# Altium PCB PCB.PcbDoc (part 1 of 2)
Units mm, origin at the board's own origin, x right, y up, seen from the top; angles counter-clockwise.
Board outline 106 x 80 mm, 4 copper layers (TOP, GND, SIG, BOTTOM), stack 1.586 mm thick; 94 components, 82 nets, 532 pads, 292 vias.
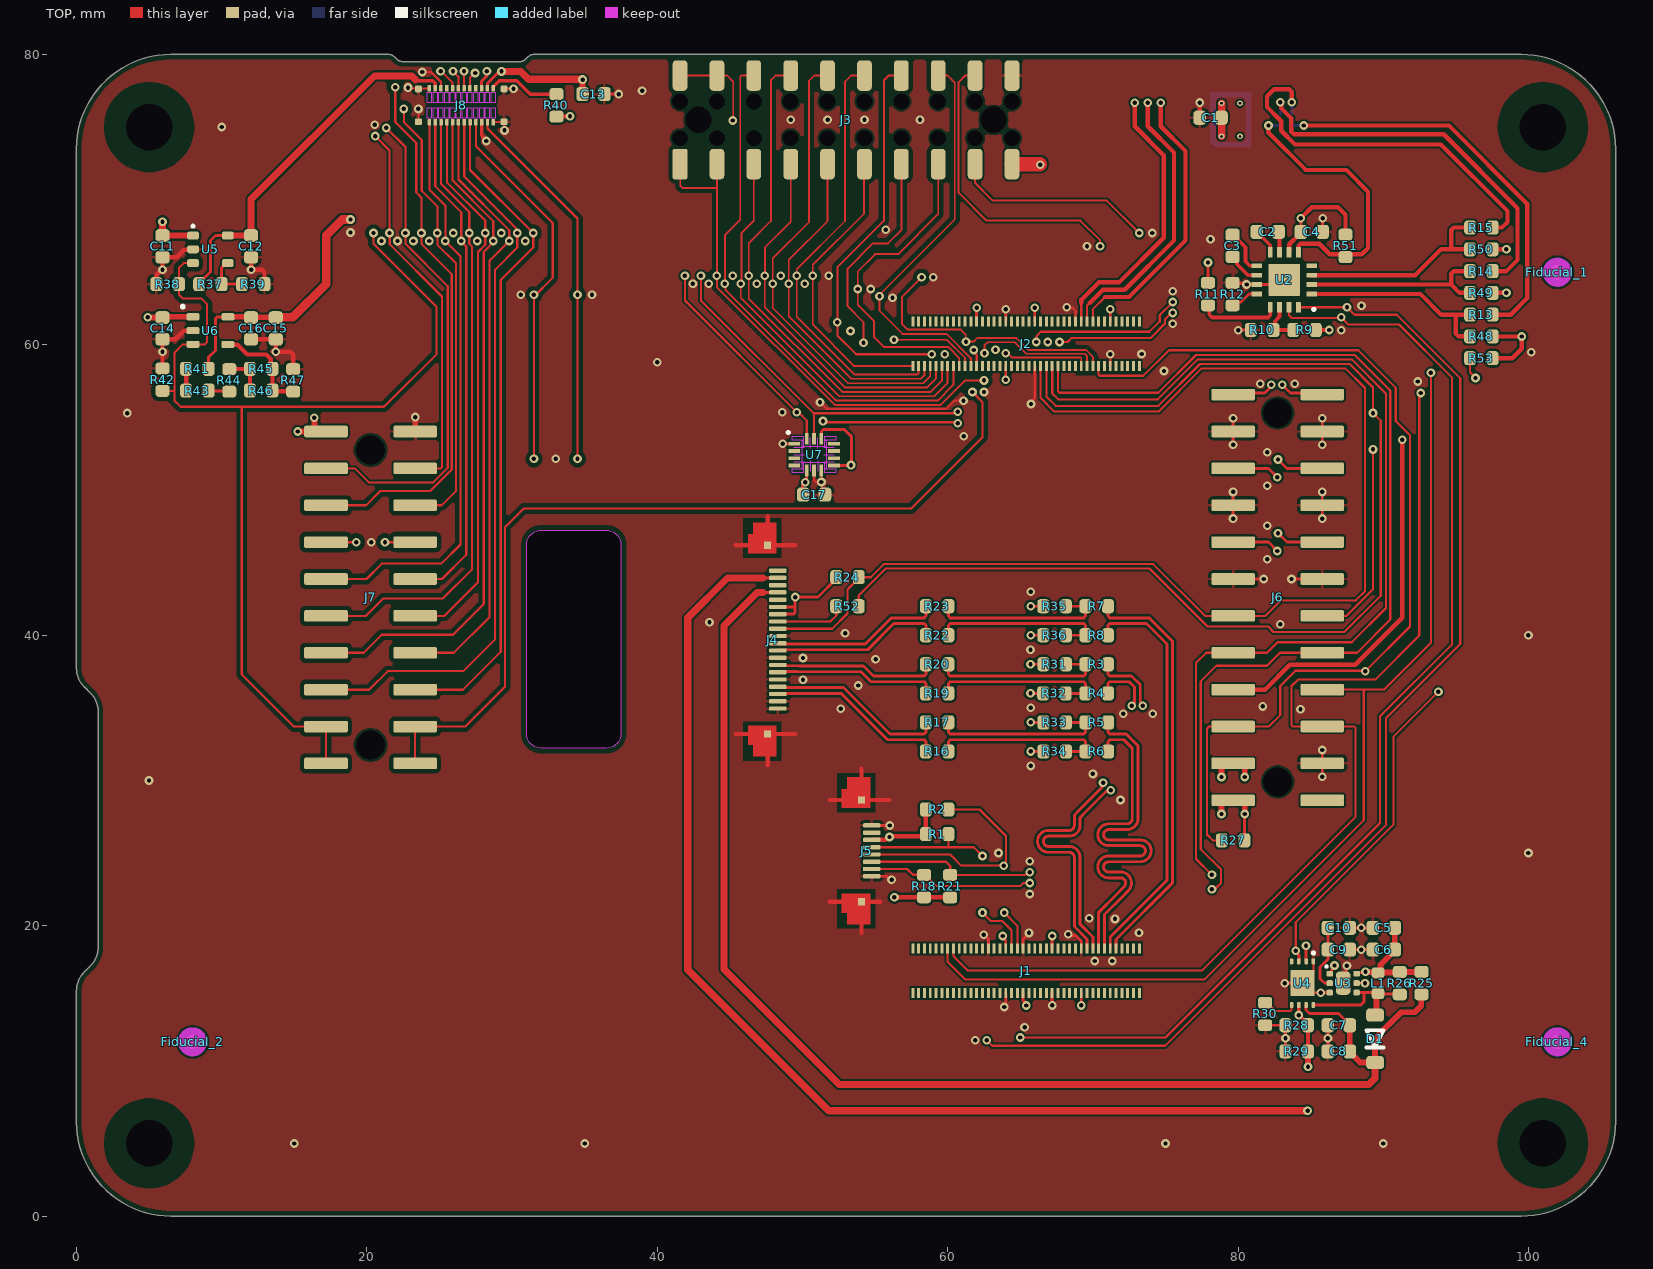
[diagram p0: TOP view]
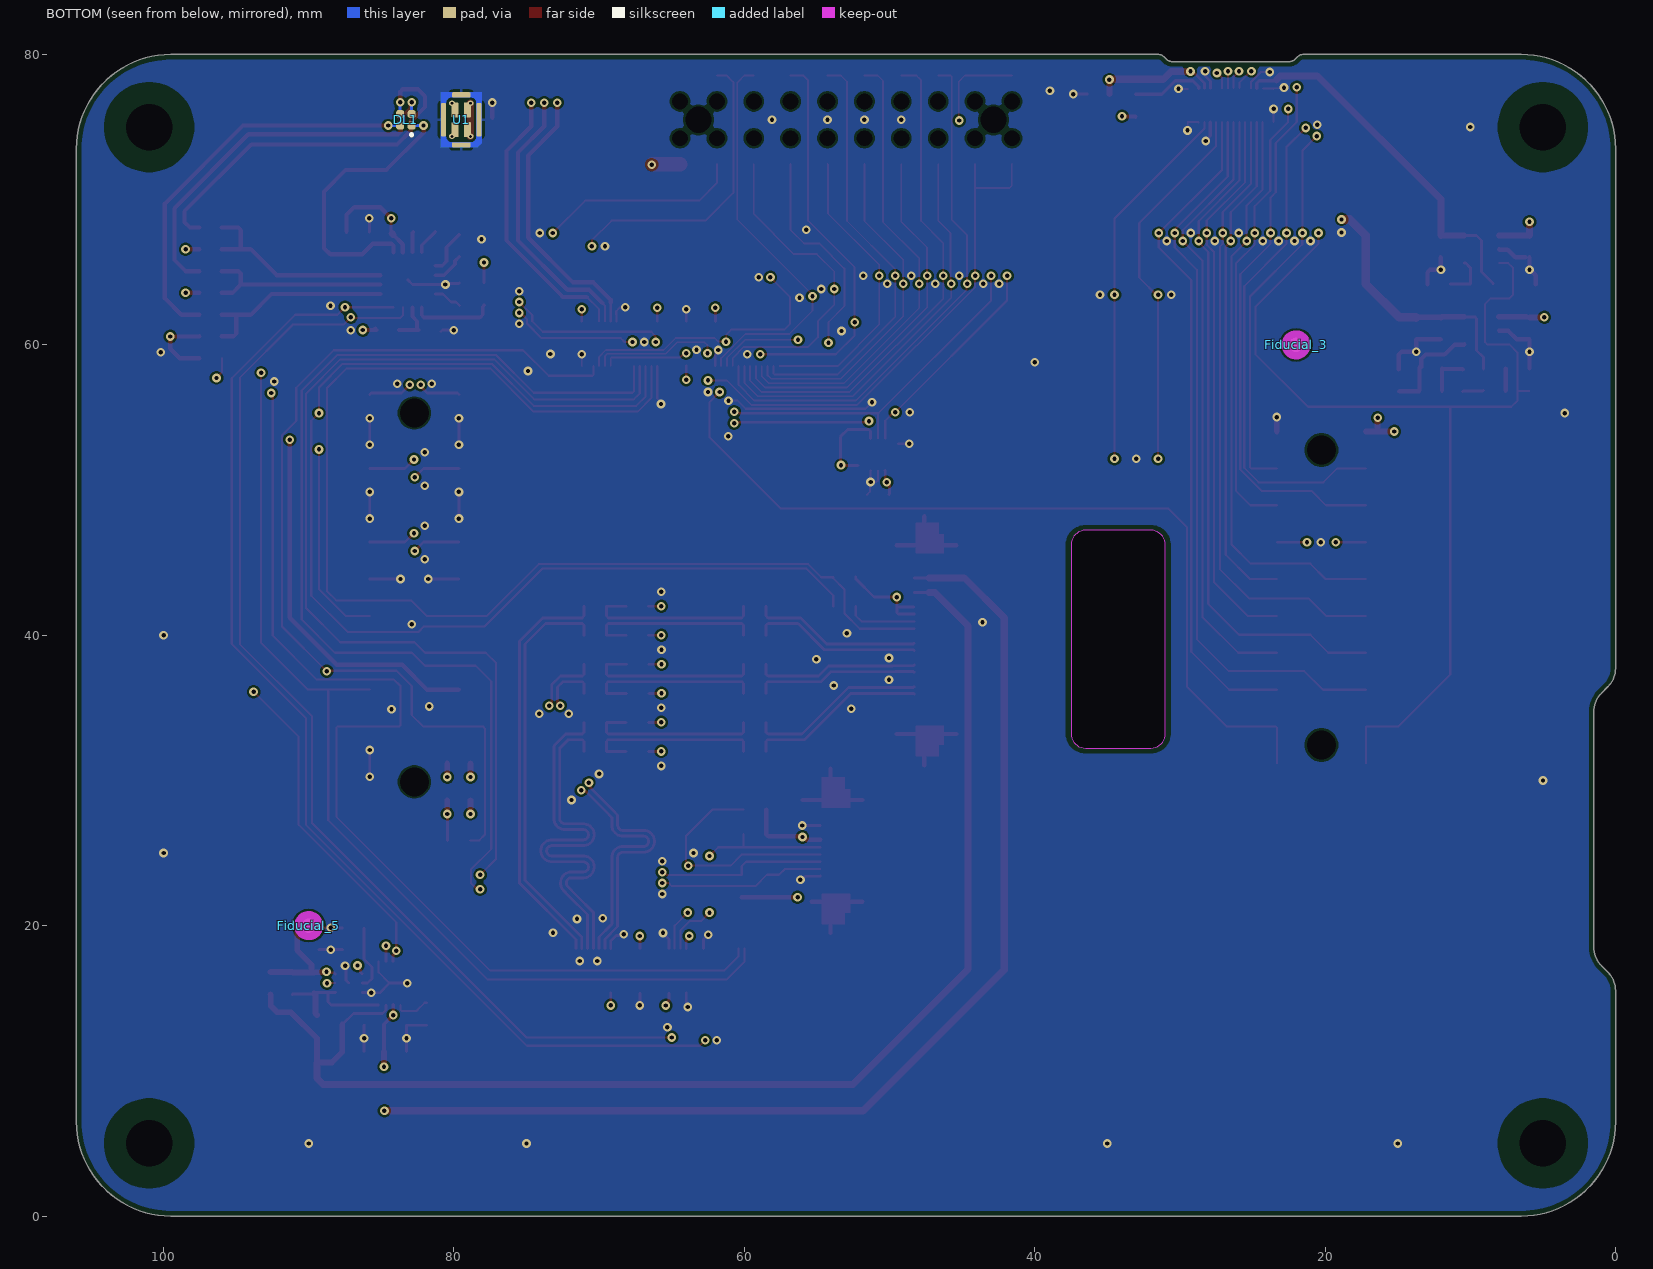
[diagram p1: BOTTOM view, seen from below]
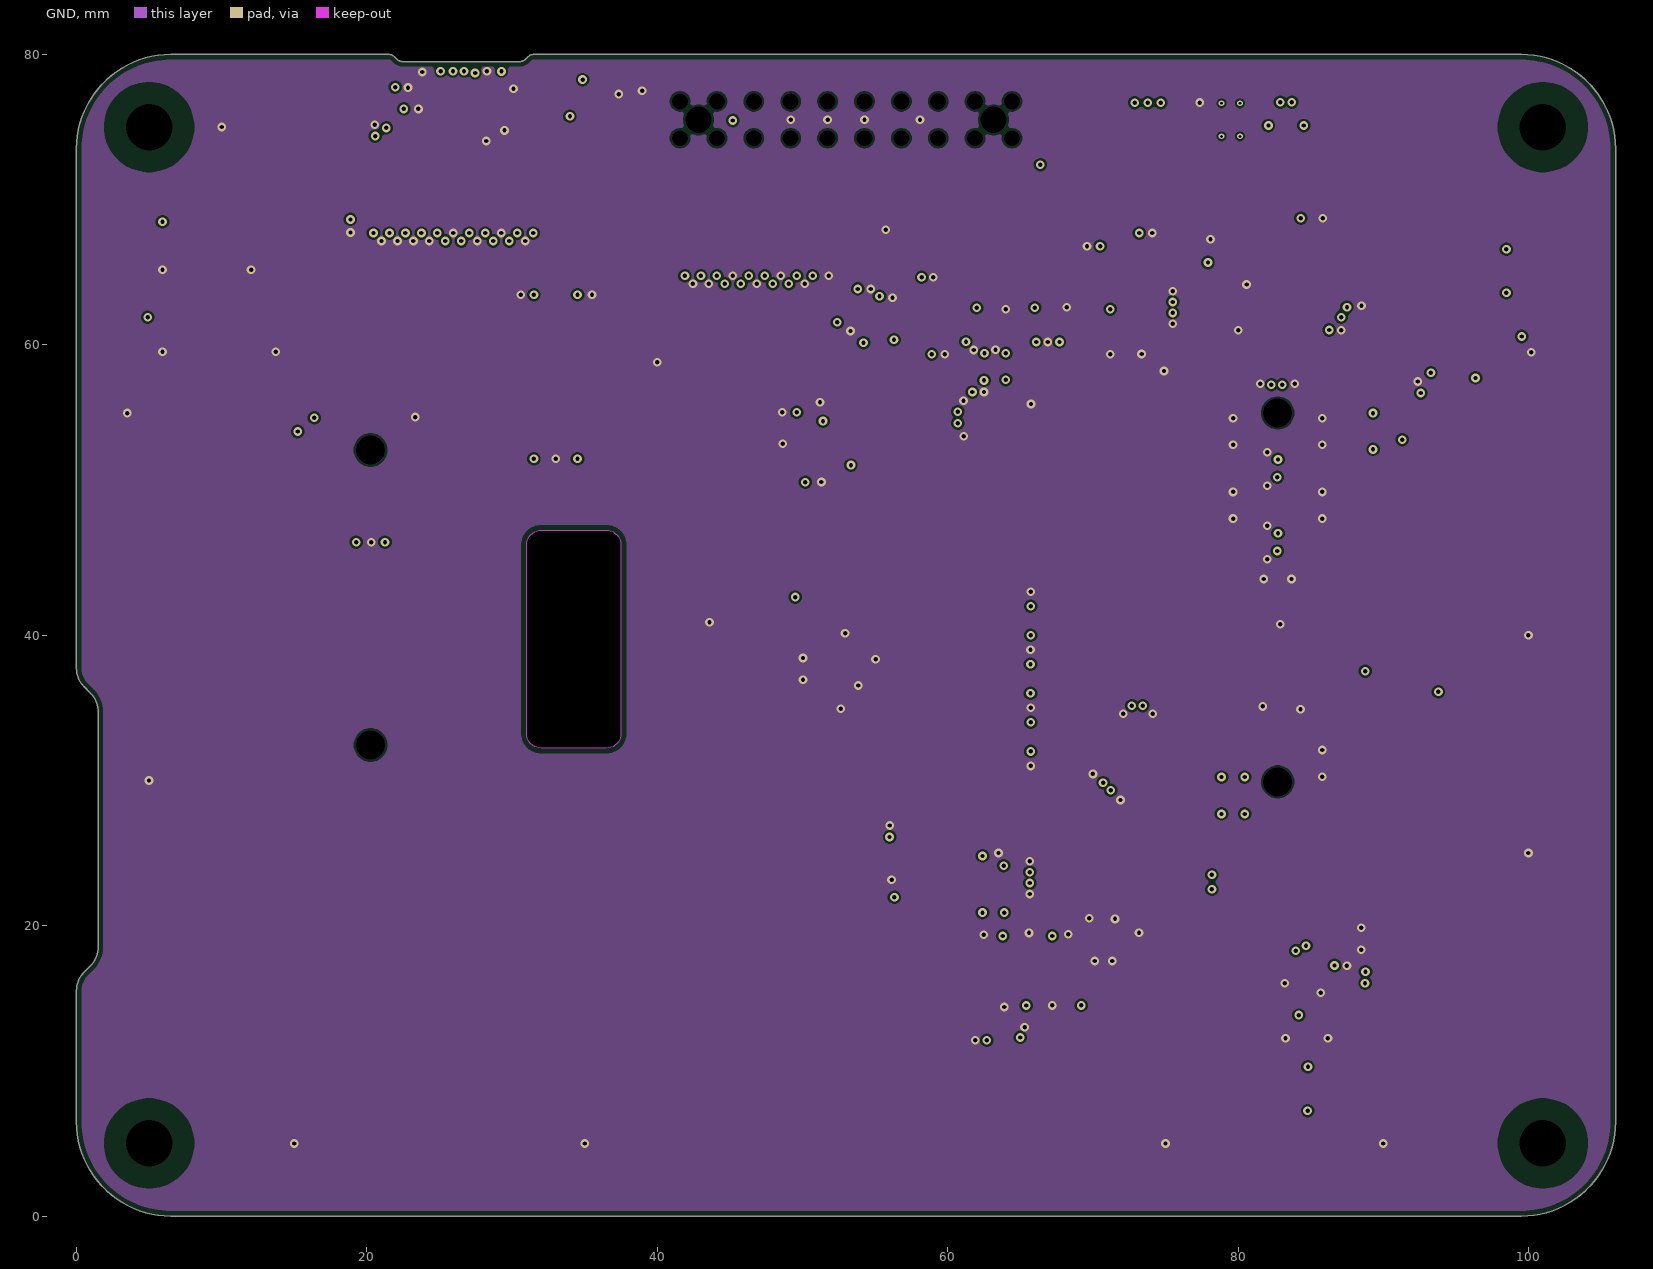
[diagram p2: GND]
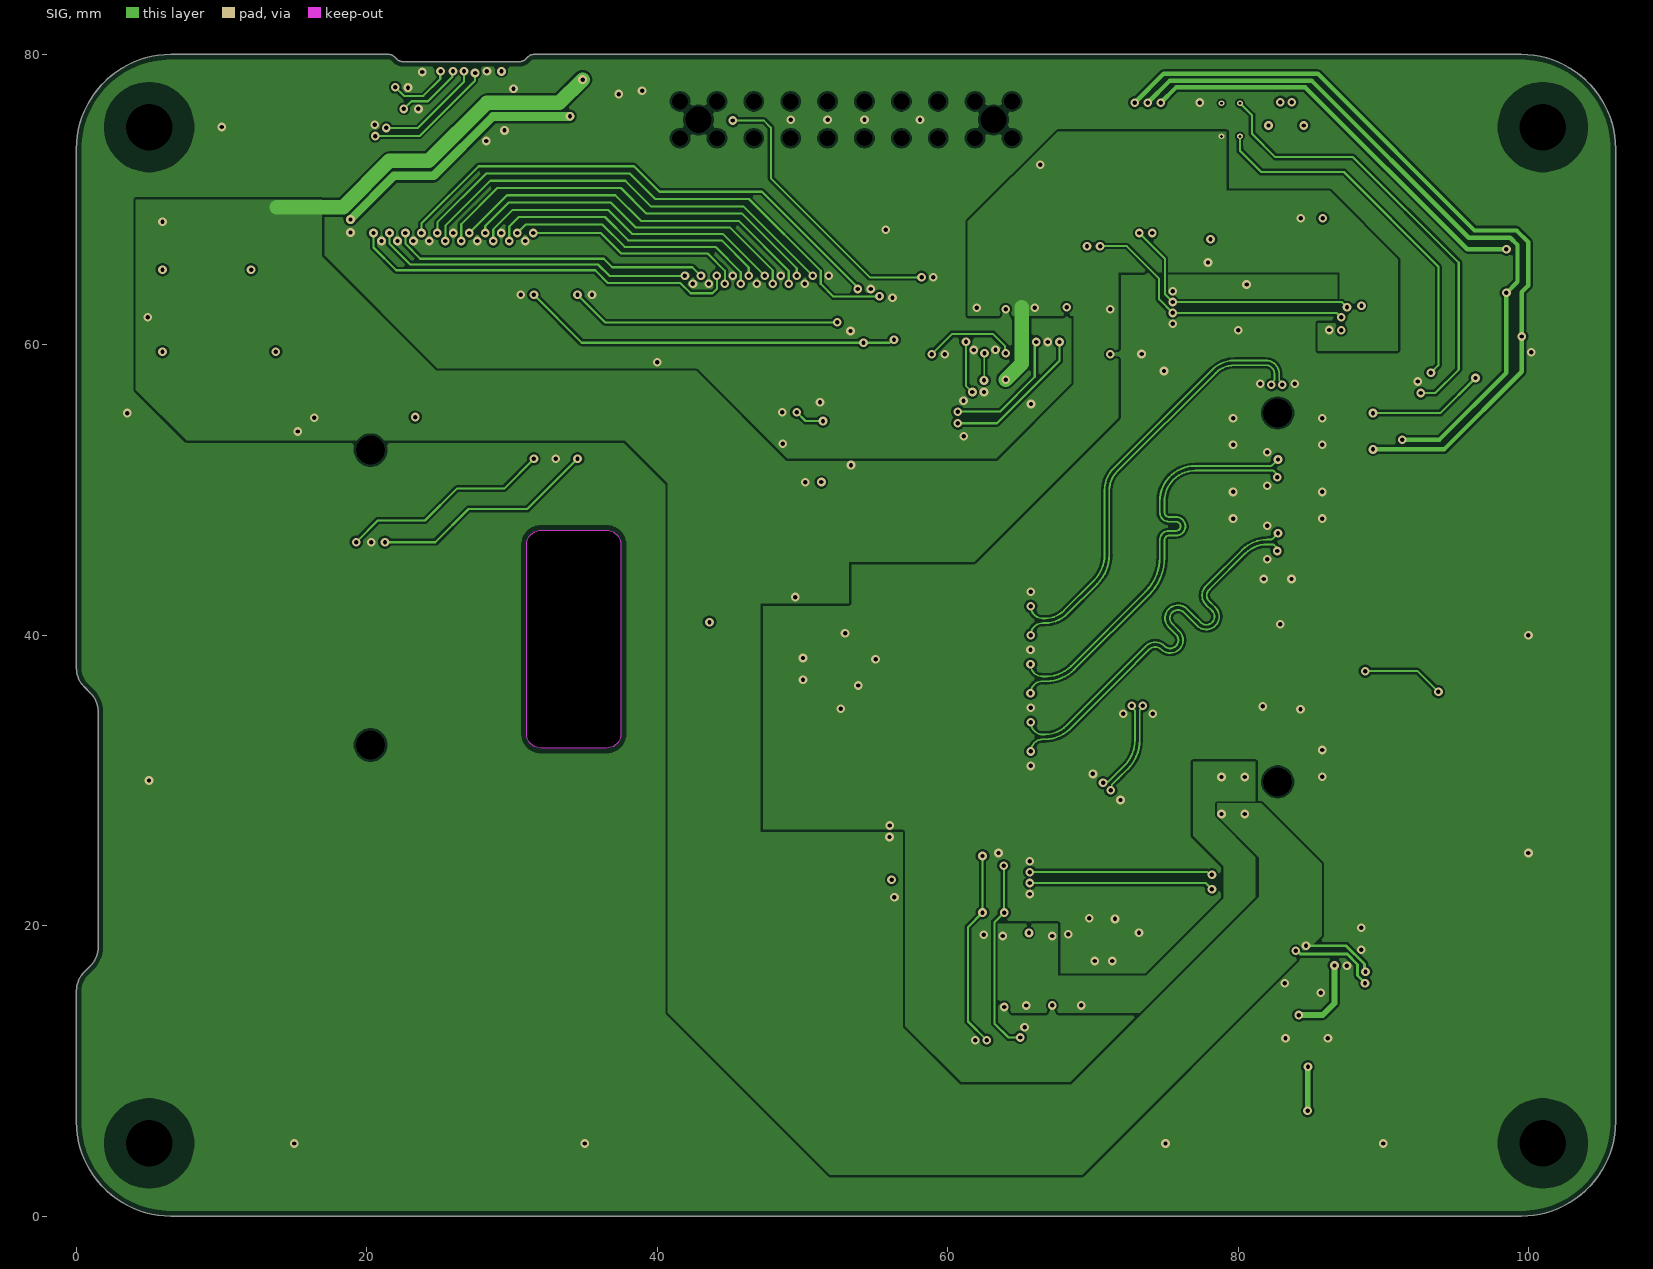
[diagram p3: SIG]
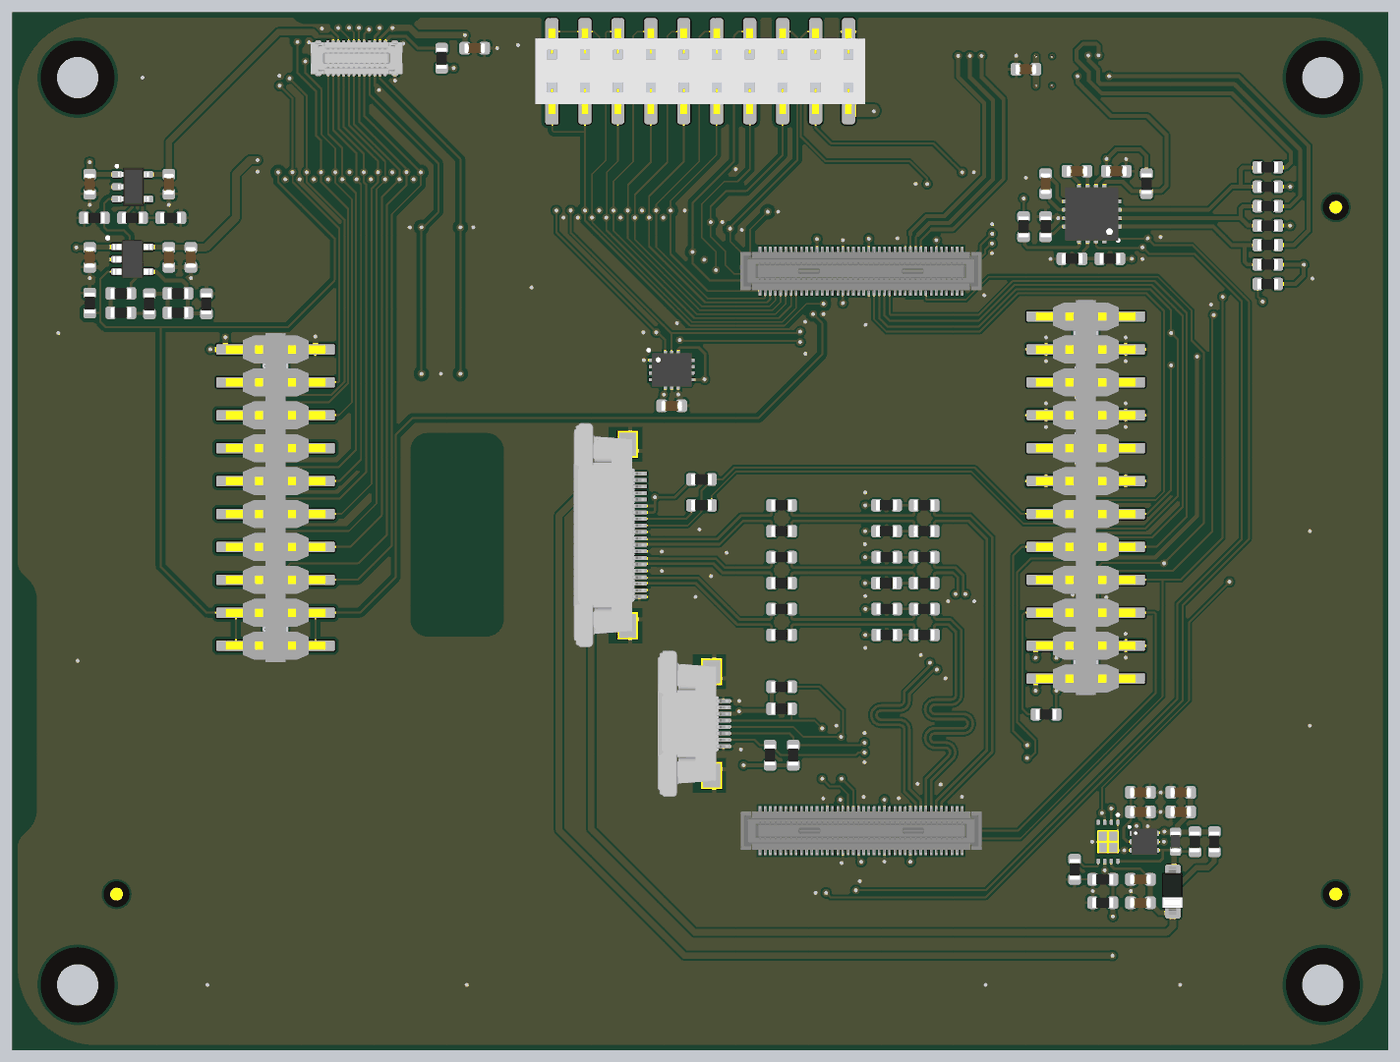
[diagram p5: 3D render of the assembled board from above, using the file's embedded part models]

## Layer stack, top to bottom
Top Solder: solder mask 0.0102, Solder Resist, Dk 3.5
TOP: signal copper 0.018
Dielectric 1: prepreg 0.14, PP-014, Dk 4.2
GND: signal copper 0.035
Dielectric2: core 1.2, FR-4, Dk 4.8
SIG: signal copper 0.035
Dielectric3: prepreg 0.14, PP-014, Dk 4.2
BOTTOM: signal copper 0.018
Bottom Solder: solder mask 0.0102, Solder Resist, Dk 3.5

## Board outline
0,6.5 0,15.521 cw(c1.811,15.521) 0.53,16.802 0.531,16.802 0.971,17.241 ccw(c-0.31,18.521) 1.501,18.521 1.501,34.727 ccw(c-0.31,34.727) 0.971,36.008 0.531,36.447 0.53,36.447 cw(c1.811,37.727) 0,37.727 0,73.5 cw(c6.5,73.5) 6.5,80 21.501,80 cw(c21.501,79.397) 21.928,79.824 22.074,79.677 ccw(c22.501,80.104) 22.501,79.5 30.501,79.5 ccw(c30.501,80.104) 30.928,79.677 31.074,79.824 cw(c31.501,79.397) 31.501,80 99.499,80 cw(c99.499,80) 99.5,80 cw(c99.5,73.5) 106,73.5 106,6.5 cw(c99.5,6.5) 99.5,0 6.5,0 cw(c6.5,6.5)
cut-out: 31.001,33.227 31.001,46.227 cw(c32.001,46.227) 32.001,47.227 36.501,47.227 cw(c36.501,46.227) 37.501,46.227 37.501,33.227 cw(c36.501,33.227) 36.501,32.227 32.001,32.227 cw(c32.001,33.227)

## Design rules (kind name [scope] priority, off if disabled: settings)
BoardOutlineClearance Silks [(OnLayer('Top Overlay') OR OnLayer('Bottom Overlay'))] p1: gap=0 ignorepadtopadclearanceinfootprint=FALSE
BoardOutlineClearance [All] p2: gap=0.35 ignorepadtopadclearanceinfootprint=FALSE
Clearance J6-MIC [All vs InComponent('C1') or InComponent('J6') or WithinRoom('MICROPHONE')] p1: gap=0.127 ignorepadtopadclearanceinfootprint=TRUE
Clearance CAMERA_TOP [InNetClass('CAMERA') vs OnLayer('TOP') and not InComponent('J8')] p2: gap=0.127 ignorepadtopadclearanceinfootprint=TRUE except(0.15: Text-Text Text-Hole; 0.3: Arc-Fill Arc-Poly Arc-Region Track-Fill Track-Poly Track-Region SMDPad-Fill SMDPad-Poly SMDPad-Region THPad-Fill THPad-Poly THPad-Region Via-Fill Via-Poly Via-Region Fill-Fill Fill-Poly Fill-Region Poly-Poly Poly-Region Region-Region)
Clearance CAMERA_SIG [InNetClass('CAMERA') vs OnLayer('SIG')] p3 off: gap=0.15 ignorepadtopadclearanceinfootprint=TRUE except(0.3: Arc-Arc Arc-Track Arc-Fill Arc-Poly Arc-Region Track-Track Track-Fill Track-Poly Track-Region SMDPad-Fill SMDPad-Poly SMDPad-Region THPad-Fill THPad-Poly THPad-Region Via-Fill Via-Poly Via-Region Fill-Fill Fill-Poly Fill-Region Poly-Poly Poly-Region Region-Region)
Clearance MH [(ObjectKind = 'Pad') And (Component = 'Free') And (Name = 'Free-MH')] p4: gap=1.5 ignorepadtopadclearanceinfootprint=FALSE
Clearance "Generic clearance 0.127" [All] p5: gap=0.15 ignorepadtopadclearanceinfootprint=TRUE
ComponentClearance [All] p1: gap=0.2 collisioncheckmode=3 verticalgap=0 showdistances=TRUE
DiffPairsRouting DSI [InDifferentialPairClass('DSI')] p1: maxlimit=0.2 minlimit=0.2 mostfreqgap=0.2 toplayer_minwidth=0.2 toplayer_maxwidth=0.2 toplayer_prefwidth=0.2 midlayer1_minwidth=0.127 midlayer1_maxwidth=0.127 midlayer1_prefwidth=0.127 midlayer2_minwidth=0.127 midlayer2_maxwidth=0.127 midlayer2_prefwidth=0.127 bottomlayer_minwidth=0.2 bottomlayer_maxwidth=0.2 bottomlayer_prefwidth=0.2 impedanceprofiledriven=TRUE impedanceprofileid={E6B00C31-4C8E-439C-824F-D2B2CDC26F9C} impedanceprofilevalue=100.000000 maxuncoupledlength=12.7
Height [All] p1: minheight=0 maxheight=30 prefheight=12.7
HoleSize HoleSize_MICROPHONE [WithinRoom('MICROPHONE')] p1: absolutevalues=TRUE maxlimit=2.54 minlimit=0.02 maxpercent=80.000 minpercent=20.000
HoleSize [All] p2: absolutevalues=TRUE maxlimit=20 minlimit=0.3 maxpercent=80.000 minpercent=20.000
HoleToHoleClearance [All] p1: gap=0.3 allowstackedmicrovias=FALSE
MatchedLengths J3-J1 [InxSignalClass('J3-J1')] p1: tolerance=25.4 checknetsindiffpair=FALSE checkdiffpairvsdiffpair=TRUE checkxsignals=TRUE checkothers=TRUE usedelayunits=TRUE delaytolerance=20.000000
MatchedLengths J3-J4 [InxSignalClass('J3-J4')] p2: tolerance=25.4 checknetsindiffpair=FALSE checkdiffpairvsdiffpair=TRUE checkxsignals=TRUE checkothers=TRUE usedelayunits=TRUE delaytolerance=20.000000
MinimumAnnularRing MinimumAnnularRing_MICROPHONE [WithinRoom('MICROPHONE')] p1: minimumring=0.1
MinimumAnnularRing [All] p2: minimumring=0.15
PlaneConnect [All] p1: pad.planeconnectstyle=Relief pad.reliefexpansion=0.508 pad.reliefentries=4 pad.reliefconductorwidth=0.15 pad.reliefairgap=0.254 via.planeconnectstyle=Direct via.reliefexpansion=0.508 via.reliefentries=4 via.reliefconductorwidth=0.254 via.reliefairgap=0.254
PolygonConnect [All] p1: thpad.connectstyle=Relief thpad.reliefconductorwidth=0.2 thpad.reliefentries=4 thpad.polygonreliefangle="90 Angle" thpad.airgapwidth=0.254 smdpad.connectstyle=Relief smdpad.reliefconductorwidth=0.2 smdpad.reliefentries=4 smdpad.polygonreliefangle="90 Angle" smdpad.airgapwidth=0.2 via.connectstyle=Direct via.reliefconductorwidth=0.254 via.reliefentries=4 via.polygonreliefangle="90 Angle" via.airgapwidth=0.254
RoomDefinition U_MICROPHONE [InComponentClass('U_MICROPHONE')] p1: confinementstyle=ConfineIn formatcopy=TRUE lockcomponents=FALSE outline -62.039,-91.249 -11.239,-91.249 -11.239,-65.849 -62.039,-65.849
RoomDefinition U_RGB_LED [InComponentClass('U_RGB_LED')] p2: confinementstyle=ConfineIn formatcopy=TRUE lockcomponents=FALSE outline -62.039,-91.249 -11.239,-91.249 -11.239,-65.849 -62.039,-65.849
RoomDefinition ACCELEROMETER [InComponentClass('ACCELEROMETER')] p3: confinementstyle=ConfineIn formatcopy=TRUE lockcomponents=FALSE outline 4.358,3.371 124.658,3.371 124.658,78.971 4.358,78.971
RoomDefinition MICROPHONE [False vs False] p4: confinementstyle=ConfineIn formatcopy=TRUE lockcomponents=FALSE outline 78.058,77.4 80.958,77.4 80.958,73.571 78.058,73.571
RoomDefinition CAMERA [InComponentClass('CAMERA')] p5: confinementstyle=ConfineIn formatcopy=TRUE lockcomponents=FALSE outline 17.961,56.251 36.961,56.251 36.961,96.251 17.961,96.251
RoomDefinition TOP [InComponentClass('TOP')] p6: confinementstyle=ConfineIn formatcopy=TRUE lockcomponents=FALSE outline -0.492,-0.57 104.928,-0.57 104.928,78.409 -0.492,78.409
RoomDefinition GIGA_HEADERS [InComponentClass('GIGA_HEADERS')] p7: confinementstyle=ConfineIn formatcopy=TRUE lockcomponents=FALSE outline 14.304,25.068 94.186,25.068 94.186,61.44 14.304,61.44
RoomDefinition DISPLAY [InComponentClass('DISPLAY')] p8: confinementstyle=ConfineIn formatcopy=TRUE lockcomponents=FALSE outline -3.032,-0.596 108.973,-0.596 108.973,77.756 -3.032,77.756
RoomDefinition PORTENTA [InComponentClass('PORTENTA')] p9: confinementstyle=ConfineIn formatcopy=TRUE lockcomponents=FALSE outline 54.833,13.733 77.542,13.733 77.542,62.902 54.833,62.902
RoutingLayers RoutingLayers_CAMERA [InNetClass('CAMERA')] p1: top layer_v5=TRUE mid layer 1_v5=FALSE mid layer 2_v5=TRUE bottom layer_v5=FALSE
RoutingLayers [All] p2: top layer_v5=TRUE mid layer 1_v5=TRUE mid layer 2_v5=TRUE bottom layer_v5=TRUE
RoutingVias Vias_MICROPHONE [WithinRoom('MICROPHONE')] p1: holewidth=0.2 width=0.4 viastyle="Through Hole" minholewidth=0.2 minwidth=0.4 maxholewidth=0.2 maxwidth=0.4
RoutingVias StandardVias [All] p2: holewidth=0.3 width=0.6 viastyle="Through Hole" minholewidth=0.3 minwidth=0.6 maxholewidth=0.3 maxwidth=0.6
SilkToSilkClearance [All] p1: silktosilkclearance=0.2
SilkToSolderMaskClearance [IsPad] p1: minsilkscreentomaskgap=0.15 clearancetoexposedcopper=TRUE
SolderMaskExpansion VIAtented [IsVia] p1: expansion=0.102 istentingtop=TRUE
SolderMaskExpansion [All] p2: expansion=0.05 istentingtop=FALSE
UnRoutedNet [All] p1: checkbadconnections=TRUE
ViasUnderSMD ViasUnderSMD_Microphone [WithinRoom('MICROPHONE')] p1: allowed=TRUE
ViasUnderSMD [All] p2: allowed=FALSE
Width Width_CAM_SDATA [InNet('CAMERA.SDATA_1')] p1: maxlimit=0.254 minlimit=0.1 preferedwidth=0.254
Width BMM_Width [WithinRoom('ACCELEROMETERS')] p2: maxlimit=2.54 minlimit=0.09 preferedwidth=0.254
Width CAMERA_width [InNetClass('CAMERA')] p3 off: maxlimit=0.254 minlimit=0.127 preferedwidth=0.254 toplayer_minwidth=0.2 toplayer_maxwidth=0.201 toplayer_prefwidth=0.201 midlayer1_minwidth=0.254 midlayer2_maxwidth=0.127 midlayer2_prefwidth=0.127 bottomlayer_minwidth=0.2 minimp=50.000000 maximp=50.000000 favimp=50.000000
Width [All] p4: maxlimit=5 minlimit=0.127 preferedwidth=0.15
20 further rules are at their usual default settings.

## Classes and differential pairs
component class U_MICROPHONE: C1 U1
component class U_RGB_LED: C2 C3 C4 DL1 R9 R10 R11 R12 R13 R14 R15 R51 U2
component class ACCELEROMETER: C17 U7
net class CAMERA: DOUT0 DOUT1 DOUT2 DOUT3 DOUT4 DOUT5 DOUT6 DOUT7 HREF PA1 PA6 PD4 PI5 PJ9
differential pair class DSI: CK CK_4 D0 D0_4 D1 D1_4 DSI.CLK_1 DSI.D0_1 DSI.D1_1 DSI_CK DSI_CK_2 DSI_CK_3 DSI_CK_4 DSI_D0 DSI_D0_2 DSI_D0_3 DSI_D0_4 DSI_D1 DSI_D1_2 DSI_D1_3 DSI_D1_4
component class CAMERA: C11 C12 C13 C14 C15 C16 J3 J8 M1 R37 R38 R39 R40 R41 R42 R43 R44 R45 R46 R47 U5 U6
component class TOP: Fiducial_1 Fiducial_2 Fiducial_3 Fiducial_4 Fiducial_5 R1 R2 R48 R49 R50 R52 R53
component class DISPLAY: C5 C6 C7 C8 C9 C10 D1 J4 J5 L1 R16 R17 R18 R19 R20 R21 R22 R23 R24 R25 R26 R27 R28 R29 R30 U3 U4
component class GIGA_HEADERS: J6 J7 R31 R32 R33 R34 R35 R36
component class PORTENTA: J1 J2 R3 R4 R5 R6 R7 R8
differential pair DSI_D1_3: +DSI_D1_3_P -DSI_D1_3_N
differential pair DSI_D0_3: +DSI_D0_3_P -DSI_D0_3_N
differential pair DSI_CK_3: +DSI_CK_3_P -DSI_CK_3_N
differential pair DSI_D1_2: +DSI_D1_2_P -DSI_D1_2_N
differential pair DSI_D0_2: +DSI_D0_2_P -DSI_D0_2_N
differential pair DSI_CK_2: +DSI_CK_2_P -DSI_CK_2_N
differential pair D1: +D1_P -D1_N
differential pair D0: +D0_P -D0_N
differential pair CK: +CK_P -CK_N
differential pair D1_4: +D1_4_P -D1_4_N
differential pair D0_4: +D0_4_P -D0_4_N
differential pair CK_4: +CK_4_P -CK_4_N

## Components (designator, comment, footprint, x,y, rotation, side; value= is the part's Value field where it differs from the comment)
C1 "C0603C104K5RAC3190" CAP-0603 78.108,75.644 r0 top value=100nF
C2 "TMK107BJ105MAHT" CAP-0603 82.042,67.783 r0 top value=1µF
C3 "TMK107BJ105MAHT" CAP-0603 79.629,66.821 r270 top value=1µF
C4 "GRM188R61C106KAALD" CAP-0603 85.078,67.783 r180 top value=10µF
C5 "TMK107BJ105MAHT" CAP-0603 90.04,19.85 r0 top value=1µF
C6 "C0603C104K5RAC3190" CAP-0603 90.04,18.35 r0 top value=100nF
C7 "TMK107BJ105MAHT" CAP-0603 86.94,13.14 r0 top value=1µF
C8 "C0603C104K5RAC3190" CAP-0603 86.94,11.34 r0 top value=100nF
C9 "C0603C104K5RAC3190" CAP-0603 86.94,18.35 r180 top value=100nF
C10 "C0603C104K5RAC3190" CAP-0603 86.94,19.85 r180 top value=100nF
C11 "TMK107BJ105MAHT" CAP-0603 5.927,66.781 r90 top value=1µF
C12 "TMK107BJ105MAHT" CAP-0603 12.026,66.781 r90 top value=1µF
C13 "GRM188R61C106KAALD" CAP-0603 35.608,77.271 r180 top value=10µF
C14 "TMK107BJ105MAHT" CAP-0603 5.927,61.131 r90 top value=1µF
C15 "TMK107BJ105MAHT" CAP-0603 13.727,61.131 r90 top value=1µF
C16 "C0603C104K5RAC3190" CAP-0603 12.027,61.131 r90 top value=100nF
C17 "C0603C104K5RAC3190" CAP-0603 50.8,49.682 r180 top value=100nF
D1 "1N4148W" SOD123-1 89.44,12.205 r90 top
DL1 "SMLP34RGB2W3" SMLP34RGB2W 83.312,75.5 r90 bottom
Fiducial_1 "Fiducial mark 1mm" "Fiducial mark 1mm-Footprint-1" 102,65 r90 top
Fiducial_2 "Fiducial mark 1mm" "Fiducial mark 1mm-Footprint-1" 8,12 r90 top
Fiducial_3 "Fiducial mark 1mm" "Fiducial mark 1mm-Footprint-1" 22,60 r90 bottom
Fiducial_4 "Fiducial mark 1mm" "Fiducial mark 1mm-Footprint-1" 102,12 r90 top
Fiducial_5 "Fiducial mark 1mm" "Fiducial mark 1mm-Footprint-1" 90,20 r90 bottom
J1 "DF40HC(3.5)-80DS-0.4V(51)-LEFT" DF40HC(3.5)-80DS-0.4V(51)-Footprint-1 65.401,16.895 r180 top locked
J2 "DF40HC(3.5)-80DS-0.4V(51)-RIGHT" DF40HC(3.5)-80DS-0.4V(51)-Footprint-1 65.401,60.075 r0 top locked
J3 "21TW-247" 21TW-247 53.001,75.5 r0 top locked
J4 "F32Q-1A7H1-11020" F32R-1A7H1-11020 46.451,39.7 r270 top locked
J5 "F32Q-1A7H1-11008" F32R-1A7H1-11008 52.921,25.154 r270 top locked
J6 "TSM-112-01-F-DV-A-P-FR" TSM-112-01-F-DV-A-P-FR 82.729,42.604 r270 top
J7 "TSM-110-01-F-DV-A-P-FR" TSM-110-01-F-DV-A-P-FR 20.256,42.601 r270 top locked
J8 "505550-2420" 503772-2420-Footprint-1 26.501,76.495 r0 top locked
L1 "MLZ1608M150WTD25" L-0603 89.64,16.04 r270 top
M1 "GC2145" GC2145-Footprint-1 26.501,88.495 r0 top
R1 "CRCW060310K0JNEAC" RES-0603#1 59.275,26.3 r180 top value=10k
R2 "CRCW060310K0JNEAC" RES-0603#1 59.275,28 r180 top value=10k
R3 "CRCW06030000Z0EAC" RES-0603#1 70.264,38 r180 top value=0
R4 "CRCW06030000Z0EAC" RES-0603#1 70.264,36 r180 top value=0
R5 "CRCW06030000Z0EAC" RES-0603#1 70.275,34 r180 top value=0
R6 "CRCW06030000Z0EAC" RES-0603#1 70.275,32 r180 top value=0
R7 "CRCW06030000Z0EAC" RES-0603#1 70.264,42 r180 top value=0
R8 "CRCW06030000Z0EAC" RES-0603#1 70.264,40 r180 top value=0
R9 "CRCW06030000Z0EAC" RES-0603#1 84.582,61.025 r0 top value=0
R10 "CRCW06030000Z0EAC" RES-0603#1 81.661,61.025 r180 top value=0
R11 "CRCW060310K0JNEAC" RES-0603#1 77.929,63.496 r90 top value=10k
R12 "CRCW060310K0JNEAC" RES-0603#1 79.629,63.496 r270 top value=10k
R13 "CRCW0603330RFKEAC" RES-0603#2 96.76,62.081 r0 top value=330
R14 "CRCW0603330RFKEAC" RES-0603#2 96.76,65.081 r0 top value=330
R15 "CRCW0603330RFKEAC" RES-0603#2 96.76,68.081 r0 top value=330
R16 "CRCW06030000Z0EAC" RES-0603#1 59.275,32 r180 top value=0
R17 "CRCW06030000Z0EAC" RES-0603#1 59.275,34 r180 top value=0
R18 "CRCW060310K0JNEAC" RES-0603#1 58.375,22.725 r270 top value=10k
R19 "CRCW06030000Z0EAC" RES-0603#1 59.275,36 r180 top value=0
R20 "CRCW06030000Z0EAC" RES-0603#1 59.275,38 r180 top value=0
R21 "CRCW060310K0JNEAC" RES-0603#1 60.175,22.721 r270 top value=10k
R22 "CRCW06030000Z0EAC" RES-0603#1 59.275,40 r180 top value=0
R23 "CRCW06030000Z0EAC" RES-0603#1 59.275,42 r180 top value=0
R24 "CRCW060310K0JNEAC" RES-0603#1 53.1,44 r180 top value=10k
R25 "CRCW06030000Z0EAC" RES-0603#1 92.64,16.04 r270 top value=0
R26 "CRCW06030000Z0EAC" RES-0603#1 91.14,16.04 r270 top value=0
R27 "CRCW060310K0JNEAC" RES-0603#1 79.659,25.871 r0 top value=10k
R28 "CRCW060310R0FKEAC" RES-0603#1 84.04,13.14 r0 top value=10
R29 "CRCW060310R0FKEAC" RES-0603#1 84.04,11.34 r0 top value=10
R30 "CRCW060310R0FKEAC" RES-0603#1 81.865,13.915 r90 top value=10
R31 "CRCW06030000Z0EAC" RES-0603#1 67.375,38 r0 top value=0
R32 "CRCW06030000Z0EAC" RES-0603#1 67.355,36 r0 top value=0
R33 "CRCW06030000Z0EAC" RES-0603#1 67.375,34 r0 top value=0
R34 "CRCW06030000Z0EAC" RES-0603#1 67.375,32 r0 top value=0
R35 "CRCW06030000Z0EAC" RES-0603#1 67.364,42 r0 top value=0
R36 "CRCW06030000Z0EAC" RES-0603#1 67.364,40 r0 top value=0
R37 "CRCW06030000Z0EAC" RES-0603#1 9.227,64.181 r180 top value=0
R38 "CRCW060310K0JNEAC" RES-0603#1 6.282,64.181 r0 top value=10k
R39 "CRCW06030000Z0EAC" RES-0603#1 12.177,64.181 r180 top value=0
R40 "CRCW06030000Z0EAC" RES-0603#1 33.058,76.496 r90 top value=0
R41 "CRCW060310K0JNEAC" RES-0603#1 8.327,58.351 r0 top value=10k
R42 "CRCW060310K0JNEAC" RES-0603#1 5.927,57.605 r270 top value=10k
R43 "CRCW060310K0JNEAC" RES-0603#1 8.327,56.851 r180 top value=10k
R44 "CRCW060310K0JNEAC" RES-0603#1 10.527,57.551 r270 top value=10k
R45 "CRCW060310K0JNEAC" RES-0603#1 12.727,58.351 r0 top value=10k
R46 "CRCW060310K0JNEAC" RES-0603#1 12.727,56.851 r0 top value=10k
R47 "CRCW060310K0JNEAC" RES-0603#1 14.927,57.551 r270 top value=10k
R48 "CRCW06030000Z0EAC" RES-0603#2 96.76,60.581 r0 top value=0
R49 "CRCW06030000Z0EAC" RES-0603#2 96.76,63.581 r0 top value=0
R50 "CRCW06030000Z0EAC" RES-0603#2 96.76,66.581 r0 top value=0
R51 "CRCW06030000Z0EAC" RES-0603#2 87.403,66.821 r90 top value=0
R52 "CRCW06030000Z0EAC" RES-0603#2 53.1,42 r180 top value=0
R53 "CRCW06030000Z0EAC" RES-0603#2 96.76,59.081 r180 top value=0
U1 "MP34DT06JTR" HCLGA 79.501,75.5 r90 bottom
U2 "IS31FL3197-QFLS2-TR" PQFN65P400X400X80_HS-17N 83.185,64.481 r180 top
U3 "LV52204MTTBG" QFN65P200X200X80_HS-7L 87.24,16.04 r270 top
U4 "ISL97634IRT14Z-T" PQFN0P300X200X80_HS-9L 84.44,16.04 r270 top
U5 "AP7335-28WG-7" SOT25 9.227,66.581 r270 top
U6 "AP7311-WG-7" SOT23-5 9.227,60.981 r0 top
U7 "BMI270" VFLGA14 50.8,52.444 r0 top

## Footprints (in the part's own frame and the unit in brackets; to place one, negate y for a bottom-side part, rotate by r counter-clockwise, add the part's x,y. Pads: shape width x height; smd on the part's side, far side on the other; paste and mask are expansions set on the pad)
21TW-247 [mm]
  round 0 hole 1.1 unplated mask+0.2: 0(-11.43,-1.27) 0(-11.43,1.27) 0(-8.89,-1.27) 0(-8.89,1.27) 0(-6.35,-1.27) 0(-6.35,1.27) 0(-3.81,-1.27) 0(-3.81,1.27) 0(-1.27,-1.27) 0(-1.27,1.27) 0(1.27,-1.27) 0(1.27,1.27) 0(3.81,-1.27) 0(3.81,1.27) 0(6.35,-1.27) 0(6.35,1.27) 0(8.89,-1.27) 0(8.89,1.27) 0(11.43,-1.27) 0(11.43,1.27)
  round 0 hole 1.8 unplated paste-2539.97: 0(-10.16,0) 0(10.16,0)
  rrect25% 1.02x2.1 smd mask+0.1: 1(-11.43,-3.05)
  rrect50% 1.02x2.1 smd mask+0.1: 2(-11.43,3.05) 3(-8.89,-3.05) 4(-8.89,3.05) 5(-6.35,-3.05) 6(-6.35,3.05) 7(-3.81,-3.05) 8(-3.81,3.05) 9(-1.27,-3.05) 10(-1.27,3.05) 11(1.27,-3.05) 12(1.27,3.05) 13(3.81,-3.05) 14(3.81,3.05) 15(6.35,-3.05) 16(6.35,3.05) 17(8.89,-3.05) 18(8.89,3.05) 19(11.43,-3.05) 20(11.43,3.05)
  body extent -12.7,-3.29 12.7,3.29, height 3.71
503772-2420-Footprint-1 [mm]
  rrect50% 0.24x0.45 smd mask+0.05: 1(-2.2,1.175) 2(-1.8,1.175) 3(-1.4,1.175) 4(-1,1.175) 5(-0.6,1.175) 6(-0.2,1.175) 7(0.2,1.175) 8(0.6,1.175) 9(1,1.175) 10(1.4,1.175) 11(1.8,1.175) 12(2.2,1.175) 13(2.208,-1.161) 14(1.808,-1.161) 15(1.408,-1.161) 16(1.008,-1.161) 17(0.608,-1.161) 18(0.208,-1.161) 19(-0.192,-1.161) 20(-0.592,-1.161) 21(-0.992,-1.161) 22(-1.392,-1.161) 23(-1.792,-1.161) 24(-2.192,-1.161)
  rrect50% 0.5x0.47 smd mask+0.05: M1(-2.95,-1.135) M2(2.95,-1.135) M3(2.95,1.135) M4(-2.95,1.135)
  TOP keep-out region: -2.375,0.22 -2.025,0.22 -2.025,0.87 -2.375,0.87
  TOP keep-out region: -1.975,0.22 -1.625,0.22 -1.625,0.87 -1.975,0.87
  TOP keep-out region: -1.575,0.22 -1.225,0.22 -1.225,0.87 -1.575,0.87
  TOP keep-out region: -1.175,0.22 -0.825,0.22 -0.825,0.87 -1.175,0.87
  TOP keep-out region: -0.775,0.22 -0.425,0.22 -0.425,0.87 -0.775,0.87
  TOP keep-out region: -0.375,0.22 -0.025,0.22 -0.025,0.87 -0.375,0.87
  TOP keep-out region: 0.025,0.22 0.375,0.22 0.375,0.87 0.025,0.87
  TOP keep-out region: 0.425,0.22 0.775,0.22 0.775,0.87 0.425,0.87
  TOP keep-out region: 0.825,0.22 1.175,0.22 1.175,0.87 0.825,0.87
  TOP keep-out region: 1.225,0.22 1.575,0.22 1.575,0.87 1.225,0.87
  TOP keep-out region: 1.625,0.22 1.975,0.22 1.975,0.87 1.625,0.87
  TOP keep-out region: 2.025,0.22 2.375,0.22 2.375,0.87 2.025,0.87
  TOP keep-out region: 2.025,-0.85 2.375,-0.85 2.375,-0.2 2.025,-0.2
  TOP keep-out region: 1.625,-0.85 1.975,-0.85 1.975,-0.2 1.625,-0.2
  TOP keep-out region: 1.225,-0.85 1.575,-0.85 1.575,-0.2 1.225,-0.2
  TOP keep-out region: 0.825,-0.85 1.175,-0.85 1.175,-0.2 0.825,-0.2
  TOP keep-out region: 0.425,-0.85 0.775,-0.85 0.775,-0.2 0.425,-0.2
  TOP keep-out region: 0.025,-0.85 0.375,-0.85 0.375,-0.2 0.025,-0.2
  TOP keep-out region: -0.375,-0.85 -0.025,-0.85 -0.025,-0.2 -0.375,-0.2
  TOP keep-out region: -0.775,-0.85 -0.425,-0.85 -0.425,-0.2 -0.775,-0.2
  TOP keep-out region: -1.175,-0.85 -0.825,-0.85 -0.825,-0.2 -1.175,-0.2
  TOP keep-out region: -1.575,-0.85 -1.225,-0.85 -1.225,-0.2 -1.575,-0.2
  TOP keep-out region: -1.975,-0.85 -1.625,-0.85 -1.625,-0.2 -1.975,-0.2
  TOP keep-out region: -2.375,-0.85 -2.025,-0.85 -2.025,-0.2 -2.375,-0.2
  body extent -3.55,-1.25 3.55,1.25, height 0.66
CAP-0603 [mm] "Chip Capacitor, Body 0603 imperial,1.6x0.8mm, IPC High Density"
  rrect51% 0.87x0.97 smd mask+0: 1(-0.75,0) 2(0.75,0)
  body extent -0.8,-0.4 0.8,0.4, height 0.8
DF40HC(3.5)-80DS-0.4V(51)-Footprint-1 [mm]
  rect 0.2x0.7 smd: 1(-7.8,1.54) 2(-7.8,-1.54) 3(-7.4,1.54) 4(-7.4,-1.54) 5(-7,1.54) 6(-7,-1.54) 7(-6.6,1.54) 8(-6.6,-1.54) 9(-6.2,1.54) 10(-6.2,-1.54) 11(-5.8,1.54) 12(-5.8,-1.54) 13(-5.4,1.54) 14(-5.4,-1.54) 15(-5,1.54) 16(-5,-1.54) 17(-4.6,1.54) 18(-4.6,-1.54) 19(-4.2,1.54) 20(-4.2,-1.54) 21(-3.8,1.54) 22(-3.8,-1.54) 23(-3.4,1.54) 24(-3.4,-1.54) 25(-3,1.54) 26(-3,-1.54) 27(-2.6,1.54) 28(-2.6,-1.54) 29(-2.2,1.54) 30(-2.2,-1.54) 31(-1.8,1.54) 32(-1.8,-1.54) 33(-1.4,1.54) 34(-1.4,-1.54) 35(-1,1.54) 36(-1,-1.54) 37(-0.6,1.54) 38(-0.6,-1.54) 39(-0.2,1.54) 40(-0.2,-1.54) 41(0.2,1.54) 42(0.2,-1.54) 43(0.6,1.54) 44(0.6,-1.54) 45(1,1.54) 46(1,-1.54) 47(1.4,1.54) 48(1.4,-1.54) 49(1.8,1.54) 50(1.8,-1.54) 51(2.2,1.54) 52(2.2,-1.54) 53(2.6,1.54) 54(2.6,-1.54) 55(3,1.54) 56(3,-1.54) 57(3.4,1.54) 58(3.4,-1.54) 59(3.8,1.54) 60(3.8,-1.54) 61(4.2,1.54) 62(4.2,-1.54) 63(4.6,1.54) 64(4.6,-1.54) 65(5,1.54) 66(5,-1.54) 67(5.4,1.54) 68(5.4,-1.54) 69(5.8,1.54) 70(5.8,-1.54) 71(6.2,1.54) 72(6.2,-1.54) 73(6.6,1.54) 74(6.6,-1.54) 75(7,1.54) 76(7,-1.54) 77(7.4,1.54) 78(7.4,-1.54) 79(7.8,1.54) 80(7.8,-1.54)
  body extent -9.32,-1.69 9.28,1.69, height 3.4
F32R-1A7H1-11008 [mm]
  rrect50% 0.3x1.2 smd paste+0 mask+0.05: 1(1.75,1.85) 2(1.25,1.85) 3(0.75,1.85) 4(0.25,1.85) 5(-0.25,1.85) 6(-0.75,1.85) 7(-1.25,1.85) 8(-1.75,1.85)
  rect 0.5x0.5 smd paste-5 mask+0.3: FIX1(-3.5,1.15) FIX2(3.5,1.15)
  TOP region: -2.95,1.75 -5.05,1.75 -5.05,1.25 -5.05,0.15 -4.25,0.15 -4.25,-0.2 -2.95,-0.2
  TOP region: 2.95,1.75 5.05,1.75 5.05,1.25 5.05,0.15 4.25,0.15 4.25,-0.2 2.95,-0.2
  body extent -5.65,-3.2 5.65,2.3, height 2.06
F32R-1A7H1-11020 [mm]
  rrect50% 0.3x1.2 smd paste+0 mask+0.05: 1(4.75,1.85) 2(4.25,1.85) 3(3.75,1.85) 4(3.25,1.85) 5(2.75,1.85) 6(2.25,1.85) 7(1.75,1.85) 8(1.25,1.85) 9(0.75,1.85) 10(0.25,1.85) 11(-0.25,1.85) 12(-0.75,1.85) 13(-1.25,1.85) 14(-1.75,1.85) 15(-2.25,1.85) 16(-2.75,1.85) 17(-3.25,1.85) 18(-3.75,1.85) 19(-4.25,1.85) 20(-4.75,1.85)
  rect 0.5x0.5 smd paste-5 mask+0.3: FIX1(-6.5,1.15) FIX2(6.5,1.15)
  TOP region: -5.95,1.75 -8.05,1.75 -8.05,1.25 -8.05,0.15 -7.25,0.15 -7.25,-0.2 -5.95,-0.2
  TOP region: 5.95,1.75 8.05,1.75 8.05,1.25 8.05,0.15 7.25,0.15 7.25,-0.2 5.95,-0.2
  body extent -8.65,-3.2 8.65,2.3, height 2.06
"Fiducial mark 1mm-Footprint-1" [mm]
  round 1 smd paste-10 mask+0.5: 1(0,0)
  TOP keep-out circle w1: c0,0 r0.5
GC2145-Footprint-1 [mm]
  body extent -3.75,-7.68 3.75,7.82, height 5.08
HCLGA [mm]
  rrect22% 1.02x0.48 smd paste+0 mask+0: 1(-0.675,-0.425) 2(0.675,-0.425) 3(0.675,0.425) 4(-0.675,0.425)
  rrect50% 0.35x1.3 smd paste+0 mask+0: 5(-1.725,0) 5(1.725,0)
  rrect50% 2.3x0.35 smd paste+0 mask+0: 5(0,-1.225) 5(0,1.225)
  TOP region: 1.9,0 1.9,1.4 -1.9,1.4 -1.9,-1.1 -1.6,-1.4 1.9,-1.4 1.9,0 1.55,0 1.55,-0.65 1.52,-0.803 1.433,-0.933 1.303,-1.02 1.15,-1.05 1.15,-1.05 -1.15,-1.05 -1.303,-1.02 -1.433,-0.933 -1.52,-0.803 -1.55,-0.65 -1.55,-0.65 -1.55,0.65 -1.52,0.803 -1.433,0.933 -1.303,1.02 -1.15,1.05 -1.15,1.05 1.15,1.05 1.303,1.02 1.433,0.933 1.52,0.803 1.55,0.65 1.55,0.65 1.55,0
  body extent -2,-1.5 2,1.5, height 1
L-0603 [mm] "Chip Inductor - Body 0603 imperial,1.6x0.8mm, IPC High Density"
  rrect51% 0.75x0.87 smd mask+0: 1(-0.71,0) 2(0.71,0)
  body extent -0.8,-0.4 0.8,0.4, height 0.8
PQFN0P300X200X80_HS-9L [mm] "PQFN, 8-Leads, Body 3.00x2.00mm, Pitch 0.00mm/0.50mm, Thermal Pad 1.80x1.65mm, IPC High Density"
  rrect50% 0.4x0.25 smd: 1(-1.5,0.75) 2(-1.5,0.25) 3(-1.5,-0.25) 4(-1.5,-0.75) 5(1.5,-0.75) 6(1.5,-0.25) 7(1.5,0.25) 8(1.5,0.75)
  rect 1.8x1.65 smd paste-2: 9(0,0)
  silkscreen extent -2.13,0.71 -2.03,0.81, body extent -1.48,-0.98 1.47,0.97, height 0.8
PQFN65P400X400X80_HS-17N [mm] "PQFN, 16-Leads, Body 4,00x4,00mm, Pitch 0,65mm, Thermal Pad 2,30x2,30mm, IPC Medium Density"
  rrect20% 0.74x0.32 smd mask+0.05: 1(-1.895,0.975) 2(-1.895,0.325) 3(-1.895,-0.325) 4(-1.895,-0.975) 9(1.895,-0.975) 10(1.895,-0.325) 11(1.895,0.325) 12(1.895,0.975)
  rrect20% 0.32x0.74 smd mask+0.05: 5(-0.975,-1.895) 6(-0.325,-1.895) 7(0.325,-1.895) 8(0.975,-1.895) 13(0.975,1.895) 14(0.325,1.895) 15(-0.325,1.895) 16(-0.975,1.895)
  rrect5% 2.2x2.2 smd paste-5 mask+0.05: 17(0,0)
  silkscreen extent -2.08,1.98 -1.98,2.08, body extent -2.05,-2.05 2.05,2.05, height 0.8
QFN65P200X200X80_HS-7L [mm] "QFN, 6-Leads, Body 2.00x2.00mm, Pitch 0.65mm, Thermal Pad 1.7X1.1mm, IPC High Density"
  rrect50% 0.4x0.45 smd mask+0.05: 1(-0.65,-0.925) 2(0,-0.925) 3(0.65,-0.925) 4(0.65,0.925) 5(0,0.925) 6(-0.65,0.925)
  rrect50% 1.6x1 smd mask+0.05: 7(0,0)
  silkscreen extent -1.19,-1.19 -1.09,-1.09, body extent -1,-1 1,1, height 0.8
RES-0603#1 [mm] "Chip Resistor - Body 0603 imperial,1.6x0.8mm, IPC High Density"
  rrect51% 0.82x0.97 smd mask+0: 1(-0.775,0) 2(0.775,0)
  body extent -0.8,-0.4 0.8,0.4, height 0.43
RES-0603#2 [mm] "Chip Resistor - Body 0603 imperial,1.6x0.8mm, IPC High Density"
  rrect51% 0.82x0.97 smd mask+0.05: 1(-0.775,0) 2(0.775,0)
  body extent -0.8,-0.4 0.8,0.4, height 0.43
SMLP34RGB2W [mm]
  rrect52% 0.54x0.54 smd mask+0.05: 1(-0.395,-0.395) 2(-0.395,0.395) 3(0.395,0.395) 4(0.395,-0.395)
  silkscreen extent -1.08,-0.44 -0.98,-0.35, body extent -0.5,-0.5 0.5,0.5, height 0.2
SOD123-1 [mm]
  rrect50% 0.91x1.22 smd: A(1.635,0) C(-1.635,0)
  silkscreen extent -0.6,-0.6 0.6,0.6, body extent -1.78,-0.78 1.92,0.82, height 1.27
SOT23-5 [mm] "SOT23, 5-Leads, Body 2.90x2.80mm, Pitch 0.95mm, IPC Medium Density"
  rrect50% 0.9x0.5 smd mask+0.102: 1(-1.2,0.95) 2(-1.2,0) 3(-1.2,-0.95) 4(1.2,-0.95) 5(1.2,0.95)
  silkscreen extent -1.95,1.6 -1.86,1.7, body extent -1.5,-1.5 1.5,1.5, height 1.1
SOT25 [mil]
  rrect50% 21.65x31.5 smd mask+1.97: 1(-37.4,-47.24) 2(0,-47.24) 3(37.4,-47.24) 4(37.4,47.24) 5(-37.4,47.24)
  silkscreen extent -65,-49 -61,-45, body extent -59,-44 59,50, height 43
TSM-110-01-F-DV-A-P-FR [mm]
  rrect25% 0.8x3 smd mask+0.1: 1(-11.43,-3.07) 2(-11.43,3.07) 3(-8.89,-3.07) 4(-8.89,3.07) 5(-6.35,-3.07) 6(-6.35,3.07) 7(-3.81,-3.07) 8(-3.81,3.07) 9(-1.27,-3.07) 10(-1.27,3.07) 11(1.27,-3.07) 12(1.27,3.07) 13(3.81,-3.07) 14(3.81,3.07) 15(6.35,-3.07) 16(6.35,3.07) 17(8.89,-3.07) 18(8.89,3.07) 19(11.43,-3.07) 20(11.43,3.07)
  round 1.5 hole 2 unplated mask+0.2: ALIGN1(-10.16,0) ALIGN2(10.16,0)
  body extent -12.7,-3.85 12.7,3.85, height 9.66
TSM-112-01-F-DV-A-P-FR [mm]
  rrect25% 0.8x3 smd mask+0.1: 1(-13.97,-3.07) 2(-13.97,3.07) 3(-11.43,-3.07) 4(-11.43,3.07) 5(-8.89,-3.07) 6(-8.89,3.07) 7(-6.35,-3.07) 8(-6.35,3.07) 9(-3.81,-3.07) 10(-3.81,3.07) 11(-1.27,-3.07) 12(-1.27,3.07) 13(1.27,-3.07) 14(1.27,3.07) 15(3.81,-3.07) 16(3.81,3.07) 17(6.35,-3.07) 18(6.35,3.07) 19(8.89,-3.07) 20(8.89,3.07) 21(11.43,-3.07) 22(11.43,3.07) 23(13.97,-3.07) 24(13.97,3.07)
  round 1.5 hole 2 unplated mask+0.2: ALIGN1(-12.7,0) ALIGN2(12.7,0)
  body extent -15.24,-3.85 15.24,3.85, height 9.66
VFLGA14 [mm]
  rect 0.8x0.25 smd mask+0.05: 1(-1.375,0.75) 2(-1.375,0.25) 3(-1.375,-0.25) 4(-1.375,-0.75) 8(1.375,-0.75) 9(1.375,-0.25) 10(1.375,0.25) 11(1.375,0.75)
  rect 0.25x0.8 smd mask+0.05: 5(-0.5,-1.1) 6(0,-1.1) 7(0.5,-1.1) 12(0.5,1.1) 13(0,1.1) 14(-0.5,1.1)
  TOP keep-out region: -0.83,-0.98 -0.83,-0.58 -0.74,-0.58 -0.74,-0.98
  TOP keep-out region: 0.74,-0.98 0.74,-0.58 0.83,-0.58 0.83,-0.98
  TOP keep-out region: 0.74,0.58 0.74,0.98 0.83,0.98 0.83,0.58
  TOP keep-out region: -0.83,0.58 -0.83,0.98 -0.74,0.98 -0.74,0.58
  TOP keep-out region: -1.5,-1.25 -1.5,-0.98 -0.74,-0.98 -0.74,-1.25
  TOP keep-out region: 0.74,-1.25 0.74,-0.98 1.5,-0.98 1.5,-1.25
  TOP keep-out region: 0.74,0.98 0.74,1.25 1.5,1.25 1.5,0.98
  TOP keep-out region: -1.5,0.98 -1.5,1.25 -0.74,1.25 -0.74,0.98
  TOP keep-out region: -0.83,-0.58 -0.83,0.58 0.83,0.58 0.83,-0.58
  TOP keep-out lines w0.01: -1.4,-0.5 -0.67,-0.5 ; -1.4,0 -0.67,0 ; -1.4,0.5 -0.67,0.5 ; -0.25,-1.15 -0.25,-0.42 ; -0.25,0.42 -0.25,1.15 ; 0.25,-1.15 0.25,-0.42 ; 0.25,0.42 0.25,1.15 ; 0.67,-0.5 1.4,-0.5 ; 0.67,0 1.4,0 ; 0.67,0.5 1.4,0.5
  silkscreen extent -1.83,1.47 -1.73,1.57, body extent -1.55,-1.3 1.55,1.3, height 0.86

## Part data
C1 C6 C8 C9 C10 C16 C17: library part C0043-A.11, "CAP CHIP 0603 100nF 50V X7R 10%", Case Code (Imperial)=0603, Case Code (Metric)=1608, Dielectric=X7R, Manufacturer=KEMET, Manufacturer 2=AVX, Manufacturer Part Number 2=06035C104KAT4A, Tolerance=10%, Voltage=50V
C2 C3 C5 C7 C11 C12 C14 C15: library part C0077-A.10, "CAP CHIP 0603 1UF 25V X5R 20%", Case Code (Imperial)=0603, Case Code (Metric)=1608, Dielectric=X5R, Manufacturer="Taiyo Yuden", Tolerance=20%, Voltage=25V
C4 C13: library part C0071-A.9, "CAP CHIP 0603 10uF 16V X5R 10%", Case Code (Imperial)=0603, Case Code (Metric)=1608, Dielectric=X5R, Manufacturer=Murata, Tolerance=10%, Voltage=16V
D1: library part D0029-A.4, "DIODE FAST SMD 200mA 100V SOD123", Manufacturer=Vishay, Manufacturer 2="Micro Commercial Co", Manufacturer Part Number 2=1N4148W-TP
DL1: library part L0014-A.10, "LED RGB DIFFUSED PICOLED SMD", Case Code (Imperial)=0404, Case Code (Metric)=1010, Color=Blue,Green,Red, Forward Current=20mA, Forward Voltage=3V, Lens Color=White, Manufacturer="ROHM Semiconductor", Max Operating Temperature=85°C, Min Operating Temperature=-40°C, Package Quantity=1, Test Current=5mA
Fiducial_1 Fiducial_2 Fiducial_3 Fiducial_4 Fiducial_5: library part UT0023-A.6, "Fiducial mark 1mm clearance 2mm"
J1: library part J0016-A.11, "CONN RCPT FEMALE D80POS 0.4MM SMD GOLD", Current Rating=300mA, Manufacturer=Hirose, Package Quantity=1, Part Number=DF40HC(3.5)-80DS-0.4V(51), Voltage Rating=30V
J2: library part J0153-A.3, "CONN RCPT FEMALE D80POS 0.4MM SMD GOLD", Current Rating=300mA, Manufacturer=Hirose, Package Quantity=1, Part Number=DF40HC(3.5)-80DS-0.4V(51), Voltage Rating=30V
J3: library part J0249-A.9, "CONN SOCKET 2ROW 20POS VERTICAL PASS THROUGH + SMD with fixing + pick and place cap, in reel", Manufacturer=4UCON
J4: library part J0161-A.2, "CONN FFC SMD HORIZONTAL TOP CONNECTION 20POS 0.5mm", Manufacturer=Amphenol
J5: library part J0235-A.3, "CONN FFC SMD HORIZONTAL TOP CONNECTION 8POS 0.5mm", Manufacturer=Amphenol
J6: library part J0279-A.2, "HEADER SMD 2.54mm VERT. 2x012POS ALIGN PINS REEL PICK AND PLACE", Manufacturer=Samtech
J7: library part J0278-A.2, "HEADER SMD 2.54mm VERT. 2x010POS ALIGN PINS REEL PICK AND PLACE", Manufacturer=Samtech
J8: library part J0079-A.8, "CONN RCPT 24POS SMD GOLD", Manufacturer=Molex
L1: library part I0064-A.2, "IND SMD 15uH Isat 70mA Imax 200mA 2MHz 0603", Case Code (Imperial)=0603, Frequency=2MHz, Inductance=15µH, Manufacturer=TDK, Max DC Current=200mA, Series Resistance=1.5, Tolerance=20%
M1: library part M0018-A.2, "MODULE CAMERA ARDUCAM-GC2145", Manufacturer=Arducam
R1 R2 R11 R12 R18 R21 R24 R27 R38 R41 R42 R43 R44 R45 R46 R47: library part R0090-A.13, "RES CHIP 0603 10k 5% 1/10W B.5k", Case Code (Imperial)=0603, Case Code (Metric)=1608, Manufacturer=Vishay, Manufacturer 2=Panasonic, Manufacturer Part Number 2=ERJ-3GEYJ103V, Power=100mW, Tolerance=5%
R3 R4 R5 R6 R7 R8 R9 R10 R16 R17 R19 R20 R22 R23 R25 R26 R31 R32 R33 R34 R35 R36 R37 R39 R40 R48 R49 R50 R51 R52 R53: library part R0096-A.13, "RES CHIP 0603 0R 1/10W", Case Code (Imperial)=0603, Case Code (Metric)=1608, Manufacturer=Vishay, Manufacturer 2=Panasonic, Manufacturer Part Number 2=ERJ-U030R00V, Power=100mW, Tolerance=J
R13 R14 R15: library part R0123-A.13, "RES CHIP 0603 330R 1% 1/10W", Case Code (Imperial)=0603, Case Code (Metric)=1608, Manufacturer=Vishay, Manufacturer 2=Panasonic, Manufacturer Part Number 2=ERJ-3EKF3300V, Power=100mW, Tolerance=1%
R28 R29 R30: library part R0188-A.11, "RES CHIP 0603 10R 1% 1/10W", Case Code (Imperial)=0603, Case Code (Metric)=1608, Manufacturer=Vishay, Max Operating Temperature=155°C, Min Operating Temperature=-55°C, Package Height=0.45mm, Package Length=1.6mm, Package Style=SMTMeter, Package Width=0.8mm, Rated Power Dissipation (P)=100mW, Resistance=10R, Resistor Type="FIXED RESISTOR", Temperature Coefficient=-100100ppm/°C, Tolerance=1%, Working Voltage=75V
U1: library part U0074-A.4, "SENS MEMS AUDIO OMNIDIRECTIONAL", Manufacturer=STMicroelectronics
U2: library part U0285-A.1, "IC LED DRIVER RGB W (4ch) charge pump self running QFN16", Case/Package=QFN16, Manufacturer=Lumissil
U3: library part U0125-A.8, "IC LED BOOST DRIVER PWM DIMMING VIN 2V7 TO 5V5 VOUT MAX 40V", Frequency=600kHz, Manufacturer="ON Semiconductor", Max Input Voltage=5.5V, Max Operating Temperature=85°C, Max Output Voltage=39V, Min Input Voltage=2.7V, Min Operating Temperature=-30°C, Min Output Voltage=37V, Nominal Input Voltage (DC)=3.6V, Output Current per Channel=700mA, Package Quantity=3000
U4: library part U0264-A.5, "IC WHITE LED DRIVER W/PW DIM 26V TDFN-EP-8", Manufacturer=Renesas, Max Operating Temperature=85°C, Max Supply Voltage=5.5V, Min Operating Temperature=-40°C, Min Supply Voltage=2.4V
U5: library part U0109-A.7, "IC V-REG LDO 2.8V 300mA  SOT25", Case/Package=SOT-25, Dropout Voltage=150mV, Manufacturer="Diodes Inc", Max Input Voltage=6V, Max Operating Temperature=85°C, Max Output Current=300mA, Min Current Limit=400mA, Min Input Voltage=2V, Min Operating Temperature=-40°C, Output Voltage=2.8V, Package Quantity=3000, Quiescent Current=35uA
U6: library part U0220-A.3, "IC LDO ADJ 0.8V Min, 5V Max, 0.3V Dropout PDSO5", Manufacturer="Diodes Incorporated", Max Operating Temperature=125°C, Min Operating Temperature=-40°C
U7: library part U0217-A.3, "IC IMU 6 AXIS 14VFLGA pin to pin alternative to LSM6DSOXTR", Manufacturer="Bosch Sensortech"

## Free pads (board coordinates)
  oval 2.9x3 hole 3.2 unplated paste-2539.97 mask+1.4: MH(5,5)
  round 2.9 hole 3.2 unplated paste-2539.97 mask+1.4: MH(5,75) MH(101,5) MH(101,75)

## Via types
v1: diameter 0.6, hole 0.3, TOP to BOTTOM, tented both sides, 288 vias
v2: diameter 0.4, hole 0.2, TOP to BOTTOM, tented both sides, 4 vias

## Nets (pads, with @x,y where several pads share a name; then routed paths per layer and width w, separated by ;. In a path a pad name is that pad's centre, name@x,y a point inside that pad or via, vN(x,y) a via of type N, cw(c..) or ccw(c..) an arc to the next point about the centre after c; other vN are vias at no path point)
+1V8CAM_CORE: C15.2 C16.2 R40.1 R41.2 U6.5 | length 36.8
  TOP w0.2: R41.2@9.102,58.351 9.102,59.144 9.568,59.61 9.568,61.814 9.685,61.931 U6.5@10.427,61.931
  TOP w0.3: R40.1@33.058,75.721 33.066,75.728 33.98,75.728 v1(33.987,75.736)
  TOP w0.4: U6.5@10.427,61.931 11.977,61.931 C16.2@12.027,61.881 ; C16.2@12.027,61.906 13.702,61.906 C15.2@13.727,61.881
  TOP w0.6: C15.2@13.727,61.881 13.748,61.902 14.905,61.902 17.2,64.197 17.2,67.537 18.3,68.637 v1(18.871,68.637)
  SIG w0.6: v1(18.871,68.637) 21.871,71.637 24.607,71.637 28.693,75.723 33.975,75.723 v1(33.987,75.736)
+2V8A: C12.2 J8.2 R37.2 U5.5 | length 25.5
  TOP w0.2: R37.2@8.452,64.181 8.452,64.256 9.227,65.031 9.227,67.181 9.577,67.531 U5.5@10.426,67.531
  TOP w0.23: 23.355,78.265 23.428,78.192 24.532,78.192 24.701,78.023 J8.2@24.701,77.67
  TOP w0.4: U5.5@10.426,67.531 C12.2@12.026,67.531
  TOP w0.5: C12.2@12.026,67.531 12.026,70.026 20.521,78.521 23.099,78.521 23.355,78.265
+3V3: C1.2 C4.2 C5.2 C6.2 C11.2 C13.2 C14.2 C17.2 J2.23 J2.34 J2.43 J2.69 J3.19 J4.14 J4.15 J5.6 J6.23 J7.1 J8.11 L1.1 R1.2 R2.2 R9.2 R11.2 R18.2 R21.2 R24.2 R25.1 R26.1 R27.2 R51.2 U1.1 U1.2 U2.6 U3.6 U4.2 U5.1 U6.1 U7.5 U7.8 U7.12 | length 107.1
  TOP w0.15: J2.69@71.201,61.615 v1(71.201,62.461)
  TOP w0.2: J8.11@28.301,77.67 28.305,77.675 28.305,78.014 29.049,78.758 29.195,78.758 v1(29.272,78.834) ; J4.14@48.301,41.45 49.383,41.45 49.5,41.567 49.5,41.932 49.485,41.947 ; J4.15@48.304,41.947 49.485,41.947 ; C17.2@50.05,49.682 50.006,49.726 50.006,50.351 v1(50.2,50.544) 50.3,50.644 U7.5@50.3,51.344 ; U7.12@51.3,53.544 51.313,53.557 51.313,54.044 51.442,54.174 52.884,54.174 53.392,53.665 53.392,51.811 53.275,51.694 U7.8@52.175,51.694 ; R24.2@52.325,44 52.325,43.891 51.062,42.628 v1(49.501,42.628) 49.501,41.963 49.485,41.947 ; J2.23@62.001,61.615 v1(62.001,62.549) ; v1(64.001,57.601) J2.34@64.001,58.535 ; J2.43@66.002,61.63 v1(66.002,62.565) ; R11.2@77.929,64.271 v1(77.929,65.671) ; R27.2@80.434,25.871 v1@80.434,27.668 ; C4.2@84.328,67.783 v1(84.328,68.728) ; v1(84.685,18.612) 84.687,18.61 84.687,17.543 U4.2@84.69,17.54 ; U3.6@88.176,16.679 88.253,16.756 88.712,16.756 v1(88.779,16.823)
  TOP w0.3: J5.6@54.771,25.904 55.717,25.904 55.917,26.104 v1(55.999,26.104) 56.056,26.162 58.362,26.162 R1.2@58.5,26.3 R2.2@58.5,28 ; v1(56.334,21.946) R21.2@60.175,21.946 ; U2.6@83.51,66.376 83.52,66.386 83.52,66.925 C4.2@84.193,67.598 ; v1(84.328,68.728) 85.083,69.483 86.878,69.483 87.403,68.958 R51.2@87.403,67.783 ; R9.2@85.432,61.1 R9.2@85.357,61.025 v1(86.275,61.025)
  TOP w0.4: v1(4.9,61.9) 4.909,61.891 5.918,61.891 C14.2@5.927,61.881 ; C11.2@5.927,67.531 U5.1@8.027,67.531 ; C14.2@6.177,61.931 U6.1@8.027,61.931 ; v1(15.231,54.031) J7.1@16.386,54.031 ; v1(16.386,54.972) J7.1@16.386,54.031 ; J7.1@17.186,54.031 J7.1@16.386,54.031 ; C13.2@34.858,77.271 v1(34.858,78.271) ; v1(78.859,27.693) J6.23@78.859,28.634 ; v1(80.459,27.693) J6.23@80.459,28.634 ; v1(88.779,16.823) 88.815,16.786 89.604,16.786 L1.1@89.64,16.75 89.805,16.915 89.805,17.307 90.79,18.292 C6.2@90.79,18.35 C5.2@90.79,19.85 ; L1.1@89.733,16.782 91.108,16.782 R26.1@91.14,16.815 R25.1@92.64,16.815
  TOP w0.5: C11.2@5.927,67.531 v1(5.927,68.473) ; v1(29.272,78.834) 30.595,78.834 31.139,78.29 34.839,78.29 v1(34.858,78.271) ; v2(78.871,74.361) v2(78.871,76.639) ; C4.2@84.193,67.598 C4.2@84.258,67.663
  TOP w1: J3.19@64.431,72.451 v1@66.346,72.451
  SIG w0.2: v1(84.685,18.612) 87.443,18.612 88.702,17.353 88.702,16.899 v1(88.779,16.823)
  SIG w1: 13.8,69.481 18.366,69.481 21.556,72.672 24.272,72.672 28.273,76.673 33.261,76.673 v1(34.858,78.271) ; v1(64.001,57.601) 65.1,58.7 65.1,62.6
  other v1: 53.34,51.719 66.386,72.41
+5V: J1.21 J1.32 J1.41 J1.48 J6.21 | length 5.5
  TOP w0.2: v1(63.801,19.285) 63.801,19.183 64.001,18.983 J1.48@64.001,18.435 ; J1.41@65.201,15.355 65.201,14.824 65.407,14.618 v1(65.407,14.5) ; J1.32@67.201,18.435 v1(67.201,19.285) ; v1(69.201,14.506) J1.21@69.201,15.355
  TOP w0.4: v1(78.859,30.233) J6.21@78.859,31.174 ; v1(80.459,30.233) J6.21@80.459,31.174
BACKLIGHT: J2.66 J6.19 R27.1 U3.5 U4.3 | length 101.4
  TOP w0.15: J2.66@70.401,58.535 70.401,57.928 70.458,57.871 73.478,57.871 75.24,59.632 88.29,59.632 90.868,57.054 90.868,54.751 91.838,53.781 91.838,40.606 v1(88.763,37.531) 88.743,37.551 83.958,37.551 82.907,36.5 82.907,34.5 82.121,33.714 J6.19@79.659,33.714 78.001,33.714 77.858,33.571 77.858,26.271 78.258,25.871 R27.1@78.884,25.871 ; v1(83.974,18.262) 83.974,20.224 90.7,26.95 90.7,33 v1(93.8,36.1) ; U3.5@88.165,16.04 v1(88.749,16.04)
  TOP w0.2: v1(83.974,18.262) 83.974,18.176 84.19,17.96 U4.3@84.19,17.54
  SIG w0.15: v1(88.763,37.531) 92.369,37.531 v1(93.8,36.1)
  SIG w0.2: v1(83.974,18.262) 84.082,18.262 84.284,18.061 87.5,18.061 88.229,17.332 88.229,16.56 v1(88.749,16.04)
CK_4_N: J4.6 R19.2 | length 11.2
  TOP w0.2: J4.6@48.301,37.45 48.351,37.5 49.632,37.5 49.644,37.488 54.039,37.488 54.727,36.8 57.239,36.8 58.383,36.8 58.5,36.683 R19.2@58.5,36
CK_4_P: J4.7 R20.2 | length 11.2
  TOP w0.2: J4.7@48.301,37.95 48.351,37.9 49.797,37.9 49.81,37.888 54.205,37.888 54.893,37.2 57.073,37.2 58.383,37.2 58.5,37.317 R20.2@58.5,38
CK_N: R4.2 R19.1 R32.2 | length 12.5
  TOP w0.2: R19.1@60.05,36 60.05,36.683 60.167,36.8 67.829,36.8 67.938,36.8 68.15,36.8 ; R32.2@68.13,36 R4.2@69.48,36 ; 68.429,36.8 68.15,36.8 ; R4.2@69.5,36 69.5,36.683 69.383,36.8 68.15,36.8
CK_P: R3.2 R20.1 R31.2 | length 12.6
  TOP w0.2: R20.1@60.05,38 60.05,37.317 60.167,37.2 68.15,37.2 ; R31.2@68.13,38 R3.2@69.48,38 ; 68.531,37.2 68.15,37.2 ; R3.2@69.5,38 69.5,37.317 69.383,37.2 68.15,37.2
D0_4_N: J4.3 R16.2 | length 12.3
  TOP w0.2: J4.3@48.301,35.95 48.338,35.988 52.674,35.988 55.861,32.8 58.383,32.8 58.5,32.683 R16.2@58.5,32
D0_4_P: J4.4 R17.2 | length 12.3
  TOP w0.2: J4.4@48.301,36.45 48.351,36.4 48.91,36.4 48.923,36.388 50.266,36.388 50.27,36.392 52.835,36.392 56.027,33.2 58.383,33.2 58.5,33.317 R17.2@58.5,34
D0_N: R6.2 R16.1 R34.2 | length 12.5
  TOP w0.2: R16.1@60.05,32 60.05,32.683 60.167,32.8 68.15,32.8 ; R34.2@68.15,32 R6.2@69.5,32 69.5,32.683 69.383,32.8 68.15,32.8 ; 68.429,32.8 68.15,32.8
D0_P: R5.2 R17.1 R33.2 | length 12.6
  TOP w0.2: R17.1@60.05,34 60.05,33.317 60.167,33.2 68.15,33.2 ; R33.2@68.15,34 R5.2@69.5,34 69.5,33.317 69.383,33.2 68.15,33.2 ; 68.531,33.2 68.15,33.2
D1_4_N: J4.9 R22.2 | length 11.7
  TOP w0.2: J4.9@48.301,38.95 48.351,39 48.901,39 51.901,39 54.493,39 56.293,40.8 57.239,40.8 58.383,40.8 58.5,40.683 R22.2@58.5,40
D1_4_P: J4.10 R23.2 | length 11.7
  TOP w0.2: J4.10@48.301,39.45 48.351,39.4 48.901,39.4 51.901,39.4 54.327,39.4 56.127,41.2 57.073,41.2 58.383,41.2 58.5,41.317 R23.2@58.5,42
D1_N: R8.2 R22.1 R36.2 | length 12.3
  TOP w0.2: R22.1@60.05,40 60.05,40.683 60.167,40.8 68.15,40.8 68.429,40.8 69.383,40.8 69.5,40.683 R8.2@69.5,40 ; R36.2@68.139,40 R8.2@69.489,40
D1_P: R7.2 R23.1 R35.2 | length 12.3
  TOP w0.2: R23.1@60.05,42 60.05,41.317 60.167,41.2 68.15,41.2 68.531,41.2 69.383,41.2 69.5,41.317 R7.2@69.5,42 ; R35.2@68.139,42 68.15,42 R7.2@69.489,42
DOUT0: J2.16 J3.6 J7.16 J8.17 | length 98.1
  TOP w0.127: J3.6@46.651,78.55 45.794,78.55 45.72,78.476 45.72,68.62 44.656,67.556 v1(44.656,64.201) 44.695,64.163 44.695,63.799 52.336,56.158 59.321,56.158 60.401,57.238 J2.16@60.401,58.535
  TOP w0.15: J7.16@23.326,36.251 26.607,36.251 29.224,38.869 29.224,64.469 31.456,66.701 v1(31.456,67.701) 27.109,72.048 J8.17@27.109,75.334
  SIG w0.15: v1(31.456,67.701) 36.099,67.701 37.5,66.3 43.457,66.3 44.656,65.101 v1(44.656,64.201)
DOUT1: J2.14 J3.5 J7.15 J8.18 | length 96.8
  TOP w0.127: J3.5@46.651,72.45 46.651,68.551 45.806,67.706 45.806,64.251 v1(45.756,64.201) 45.756,63.238 52.536,56.458 59.077,56.458 60.001,57.382 J2.14@60.001,58.535
  TOP w0.15: J7.15@17.186,36.251 20.151,36.251 21.431,37.531 26.631,37.531 28.834,39.734 28.834,65.179 30.356,66.701 v1(30.356,67.701) 30.27,67.787 30.27,68.03 26.709,71.591 J8.18@26.709,75.334
  SIG w0.15: v1(30.356,67.701) 30.956,68.3 36.2,68.3 37.752,66.748 44.009,66.748 45.756,65.001 v1(45.756,64.201)
DOUT2: J2.12 J3.8 J7.14 J8.19 | length 96.5
  TOP w0.127: J3.8@49.191,78.55 48.15,78.55 47.831,78.231 47.831,68.531 46.306,67.006 v1(46.306,64.751) 46.306,63.188 52.736,56.758 58.827,56.758 59.601,57.531 J2.12@59.601,58.535
  TOP w0.15: J7.14@23.326,38.791 25.991,38.791 28.448,41.248 28.448,65.793 v1(29.806,67.151) 29.806,67.893 26.309,71.39 J8.19@26.309,75.334
  SIG w0.15: v1(29.806,67.151) 29.806,68.151 30.456,68.8 36.4,68.8 38.004,67.196 44.434,67.196 46.306,65.323 v1(46.306,64.751)
DOUT3: J2.10 J3.7 J7.13 J8.20 | length 94.6
  TOP w0.127: J3.7@49.191,72.45 49.191,68.491 47.422,66.722 47.422,64.767 v1(47.406,64.751) 47.406,62.588 52.936,57.058 58.558,57.058 59.201,57.701 J2.10@59.201,58.535
  TOP w0.15: J7.13@17.186,38.791 19.791,38.791 21.031,40.031 25.931,40.031 28.048,42.148 28.048,66.401 28.706,67.059 v1(28.706,67.151) 28.706,68.518 25.909,71.315 J8.20@25.909,75.334
  SIG w0.15: v1(28.706,67.151) 28.706,67.955 30.047,69.296 36.604,69.296 38.256,67.644 44.513,67.644 v1(47.406,64.751)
